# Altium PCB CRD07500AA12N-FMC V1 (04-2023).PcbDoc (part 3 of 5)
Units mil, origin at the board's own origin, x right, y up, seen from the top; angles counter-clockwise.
Board outline 8000 x 8000 mil, 4 copper layers (Top Layer, Layer 1, Layer 2, Bottom Layer), stack 107.988 mil thick; 393 components, 213 nets, 1142 pads, 380 vias.
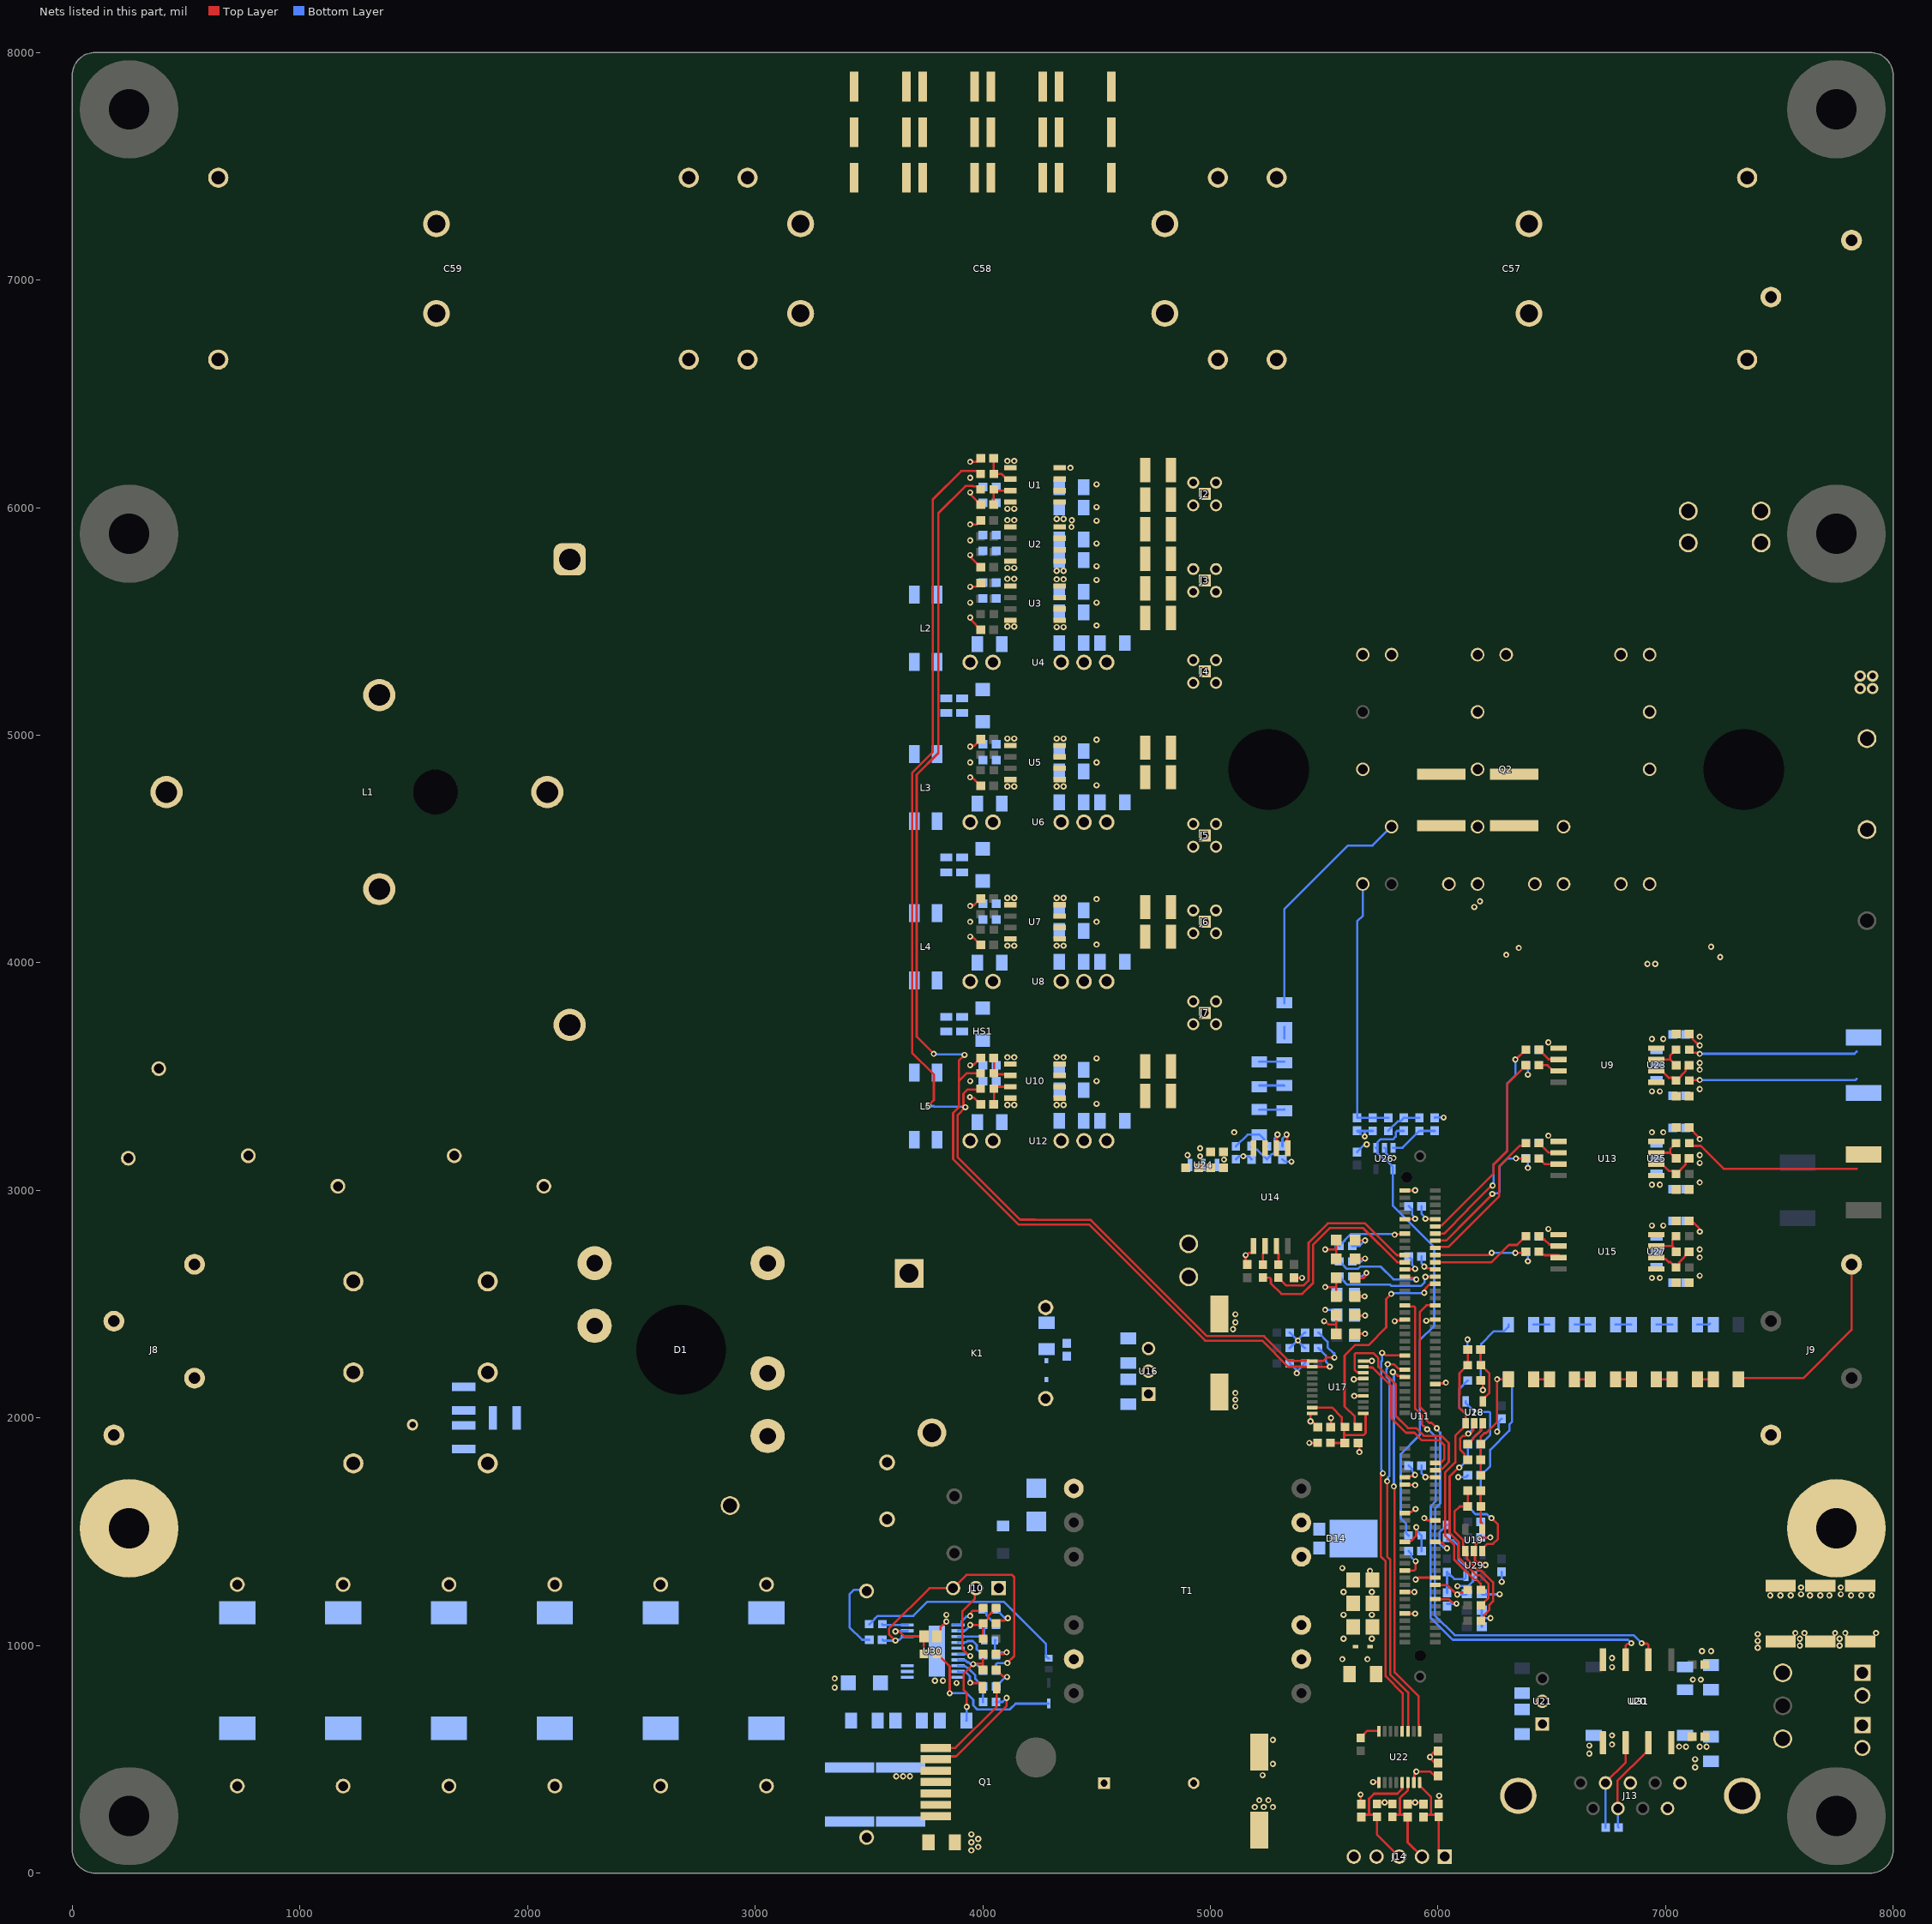
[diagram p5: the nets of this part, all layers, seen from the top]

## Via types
v1: diameter 27, hole 13, Top Layer to Bottom Layer, tented both sides, 367 vias
v2: diameter 50, hole 28, Top Layer to Bottom Layer, tented both sides, 13 vias

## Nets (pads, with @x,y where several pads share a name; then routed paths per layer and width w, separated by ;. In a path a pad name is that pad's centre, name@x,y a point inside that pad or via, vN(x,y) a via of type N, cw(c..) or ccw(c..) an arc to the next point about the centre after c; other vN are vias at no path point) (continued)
+5V: C32.1 C52.1 C65.1 C66.1 C68.1 C70.1 C72.1 C74.1 C79.1 C81.1 C86.1 C88.1 C96.1 C98.1 C114.1 C118.1 C120.1 C126.1 C146.1 J14.4 R78.2 R79.2 R80.2 R104.2 TP13.1 U1.1 U2.1 U3.1 U5.1 U7.1 U10.1 U11.48 U11.84 U11.98 U11.112 U11.120 U16.3 U17.20 U22.15 U31.2 | length 825.5
  Top Layer w10: U17.20@5447.8,2019.84 5442.87,2019.84 5440,2016.97 v1(5440,1985) 5443.25,1981.75 5450.15,1981.75 5471.9,1960 C32.1@5472.85,1960 ; R78.2@5732,303.62 5738.38,310 5793.62,310 R79.2@5800,303.62 ; v1(5810,2425) 5813.25,2428.25 5851.28,2428.25 U11.84@5855,2431.97 U11.84@5859.84,2436.81 ; U11.48@5855,1739.06 5859.84,1743.9 5889.02,1743.9 5894.74,1749.61 v1(5899.34,1749.61) ; U11.98@5855,2652.44 5856.28,2653.72 5898.72,2653.72 v1(5900,2655) ; U11.112@5855,2872.91 5856.04,2873.96 5898.96,2873.96 v1(5900,2875) ; U11.120@5855,2998.9 5855.55,2999.45 5899.45,2999.45 v1(5900,3000) ; U22.15@5896.18,397.8 5896.18,432.38 5905,441.2 v1(5905,445.8) 5965.62,445.8 5970.19,441.24 5971.14,441.24 5985,427.37 C52.1@5985,426.42 ; R80.2@6004,303.62 6005,304.62 v1(6005,340)
  Bottom Layer w10: v1(5505,2475) 5536.77,2475 5556.54,2455.23 R104.2@5556.54,2452 ; C126.1@5871.42,1790 5872.37,1790 5886.24,1776.14 5886.24,1767.31 5899.34,1754.21 v1(5899.34,1749.61) ; C118.1@5871.42,2710 5872.37,2710 5886.24,2696.14 5886.24,2673.36 5900,2659.6 v1(5900,2655) ; C114.1@5871.42,2930 5872.37,2930 5886.24,2916.14 5886.24,2893.36 5900,2879.6 v1(5900,2875)
  other v1: 5766,310 7120,850 7155,850 4108.46,3585 4138.46,3585 4108.46,4285 4138.46,4285 4108.46,4985 4138.46,4985 4108.46,5687.2 4138.46,5687.2 4108.46,5945 4138.46,5945 4108.46,6205 4138.46,6205
+5V_ISO: C49.1 C150.1 J13.9 U20.8 U31.5
  other v1: 7130,465 7130,500 6665,525 7090,555 7059.53,555.55 6665,560
+5V_LS: C19.1 C22.1 C109.1 U14.1 U24.1 | length 121.4
  Top Layer w10: v1(5335,3245) 5337.5,3242.5 5337.5,3187.07 U14.1@5340,3184.57
  Bottom Layer w10: C109.1@5317,3193.58 5317,3227 v1(5335,3245)
  other v1: 5060,3135
+5V_U_HS: C13.1 C16.1 C100.1 U9.1 U23.1 | length 70
  Top Layer w10: C13.1@7103.58,3686 7104.53,3686 7118.39,3672.14 7118.39,3666.61 7148,3637 v1(7150,3637)
  other v1: 6940,3435 6975,3435
+5V_V_HS: C18.1 C23.1 C113.1 U13.1 U25.1 | length 70.8
  Top Layer w10: C18.1@7103.58,3276 7104.53,3276 7146.75,3233.78 7146.75,3228.25 v1(7150,3225)
  other v1: 6940,3025 6975,3025
+5V_W_HS: C24.1 C28.1 C119.1 U15.1 U27.1 | length 77.5
  Top Layer w10: C24.1@7103.58,2876 7104.53,2876 7147.31,2833.21 7147.31,2821.75 v1(7150.57,2818.49)
  other v1: 6940,2615 6975,2615
+12V: C29.2 C43.1 C44.1 C45.1 C51.2 C121.1 C123.1 C149.1 D8.1 D12.2 D14.3 J11.1 J12.1 K1.3 L2.1 L3.1 L4.1 L5.1 R75.2 R82.2 R83.2 R84.2 R85.2 R87.2 R88.2 R103.2 TP8.1 U16.1 U21.1
  other v1: 5230,430 5275,480 5275,585 5580,940 5585,1030 5585,1135 5585,1235 5580,1340 5110,2050 5110,2080 5110,2110
+15V_LS: C21.1 C67.1 C71.1 C75.1 C76.1 U1.5 U2.5 U3.5 U4.7 U24.3
  other v1: 4900,3155 4325,5475 4355,5475 4325,5722 4355,5722 4325,5950.31 4355,5950.31
+15V_U_HS: C93.1 C99.1 C101.1 U10.5 U12.7 U23.3
  other v1: 4325,3375 4355,3375 6990,3665
+15V_V_HS: C89.1 C90.1 C107.1 U7.5 U8.7 U25.3
  other v1: 6990,3255 4325,4075 4355,4075
+15V_W_HS: C82.1 C83.1 C115.1 U5.5 U6.7 U27.3
  other v1: 6990,2845 4325,4775 4355,4775
-3V_LS: C64.2 C69.2 C73.2 C77.2 U1.8 U2.8 U3.8 U4.5
  other v1: 4325,5685 4355,5685 4390,5915 4391.58,5944.76 4385,6175
-3V_U_HS: C97.2 C102.2 U10.8 U12.5
  other v1: 4325,3585 4355,3585
-3V_V_HS: C87.2 C91.2 U7.8 U8.5
  other v1: 4325,4285 4355,4285
-3V_W_HS: C80.2 C84.2 U5.8 U6.5
  other v1: 4325,4985 4355,4985
A: F1.1 J8.1
A_FILT: C42.1 C134.1 D1.1 L1.4
A_FUSE: C39.1 C137.1 F1.2 L1.1 R128.2 RV1.2 RV3.2
AINN_U: C15.2 R34.2 U9.3 | length 151.5
  Top Layer w10: U9.3@6959.57,3575 7020.47,3575 ; C15.2@7046.42,3550 7045.47,3550 7020.47,3575 ; R34.2@7046.38,3618 7045.47,3618 7032.52,3605.04 7032.52,3604.14 7020.47,3592.09 7020.47,3575
AINN_V: C20.2 R42.2 U13.3 | length 149
  Top Layer w10: U13.3@6962.07,3165 7020.47,3165 ; C20.2@7046.42,3140 7045.47,3140 7020.47,3165 ; R42.2@7046.38,3208 7045.47,3208 7032.52,3195.04 7032.52,3194.14 7020.47,3182.09 7020.47,3165
AINN_W: C25.2 R47.2 U15.3 | length 145.7
  Top Layer w10: U15.3@6966.94,2755 7030.47,2755 ; C25.2@7046.42,2740 7045.47,2740 7030.47,2755 ; R47.2@7046.38,2808 7046.38,2798.91 7030,2782.53 7030,2755.47 7030.47,2755
AINP_U: C15.1 R38.2 U9.2 | length 183.3
  Top Layer w10: U9.2@6959.57,3525 6983.19,3525 7013.23,3494.96 7033.42,3494.96 R38.2@7046.38,3482 7047.28,3482 7069.76,3504.48 7069.76,3506.17 7088.76,3525.17 C15.1@7088.76,3536.14 ; C15.1@7103.58,3550 7105,3550 C15.1@7105,3545
AINP_V: C20.1 R45.2 U13.2 | length 194.9
  Top Layer w10: U13.2@6962.07,3115 6985.69,3115 7015.73,3084.96 7033.42,3084.96 R45.2@7046.38,3072 7047.28,3072 7069.76,3094.48 7069.76,3096.17 7088.76,3115.17 7088.76,3126.14 7102.63,3140 C20.1@7103.58,3140
AINP_W: C25.1 R51.2 U15.2 | length 189.1
  Top Layer w10: U15.2@6987.28,2710.91 6987.28,2700.91 6990,2698.19 7000,2698.19 7013.23,2684.96 7021.15,2684.96 7031.15,2674.96 7044.33,2674.96 R51.2@7047.28,2672 ; R51.2@7046.38,2662 7046.38,2670.25 7055.53,2670.25 7060.24,2674.96 7060.24,2684.11 7072.27,2696.14 7072.45,2696.14 7081.24,2704.92 7081.24,2706.8 7088.76,2714.33 7088.76,2725.19 C25.1@7103.58,2740
B: F2.1 J8.2
B_FILT: C41.1 C135.1 D1.2 L1.5
B_FUSE: C38.1 C138.1 F2.2 L1.2 R127.2 RV2.2 RV3.1
BLEED1: R3.2 R4.1 R7.2 R8.1 R11.2 R12.1
BLEED2: R1.2 R2.1 R5.2 R6.1 R9.2 R10.1
Bridge-: D1.5 K1.2 RV4.1 TP10.1
C: F3.1 J8.3
C_FILT: C40.1 C136.1 D1.3 L1.6
C_FUSE: C37.1 C139.1 F3.2 L1.3 R129.2 RV1.1 RV2.1
CAN_H: J13.7 R144.2 U20.7 | length 433.4
  Top Layer w10: J13.7@6788.54,284.09 6788.54,404.57 6911.69,527.72 6916.22,527.72 6925,536.5 U20.7@6925,572.91
  Bottom Layer w10: J13.7@6790.47,284.09 6790.47,203.15 R144.2@6793.62,200
CAN_L: J13.2 R144.1 U20.6 | length 410.8
  Top Layer w10: J13.2@6734.02,395.91 6825,486.89 U20.6@6825,572.91
  Bottom Layer w10: J13.2@6735.94,395.91 6735.94,200.43 R144.1@6736.38,200
CAN_RX: U11.87 U20.2 | length 2524.6
  Top Layer w10: U11.87@5988.86,2494.96 5949.96,2494.96 5920,2465 5920,2050 5950.24,2019.76 5950.24,1989.12 5960.86,1978.5 5971.5,1978.5 v1(5995,1955) ; v1(6895,1010) 6896.86,1008.14 6919.14,1008.14 6925,1002.28 U20.2@6925,937.09
  Bottom Layer w10: v1(5995,1955) 5995,1950.4 6010,1935.4 6010,1625 5988.5,1603.5 5988.5,1508.19 5987.04,1506.74 5987.04,1131.24 6073.28,1045 6860,1045 v1(6895,1010)
CAN_TX: U11.88 U20.3 | length 2483.2
  Top Layer w10: U11.88@5855,2494.96 5859.84,2490.12 5894.14,2490.12 5900,2484.26 5900,2040 5930.24,2009.76 5930.24,1970.54 5937.31,1963.47 5939.32,1963.47 v1(5952.79,1950) ; U20.3@6825,937.09 6825,1000 6831.75,1006.75 6846.75,1006.75 v1(6850,1010)
  Bottom Layer w10: v1(5952.79,1950) 5957.39,1950 5990,1917.39 5990,1633.28 5968.5,1611.78 5968.5,1516.48 5967.04,1515.02 5967.04,1122.96 6065,1025 6835,1025 v1(6850,1010)
CLK_I_U: R36.2 U11.109 | length 886.8
  Top Layer w10: U11.109@5988.86,2841.42 5993.7,2846.26 6016.88,2846.26 6245,3074.38 6245,3115 6305,3175 6305,3468.62 R36.2@6386.38,3550
CLK_I_V: R44.2 U11.105 | length 618.6
  Top Layer w10: U11.105@5988.86,2778.43 5989.65,2779.21 6036.21,2779.21 6140.48,2883.48 6238.85,2981.85 v1(6238.85,2984.15) ; v1(6343.11,3140) R44.2@6386.38,3140
  Bottom Layer w10: v1@6243.32,2984.15 v1(6238.85,2984.15) 6242.04,2987.35 6264.14,2987.35 6270,2993.21 6270,3105 6305,3140 v1(6343.11,3140)
CLK_I_W: R48.2 U11.101 | length 403.7
  Top Layer w10: U11.101@5988.86,2715.43 6221.73,2715.43 6231.52,2725.22 v1(6236.12,2725.22) ; v1(6340,2725) 6381.38,2725 R48.2@6386.38,2730
  Bottom Layer w10: v1(6236.12,2725.22) 6236.23,2725.11 6339.89,2725.11 v1(6340,2725)
CLK_V_DC: R50.2 U11.102 | length 839.9
  Top Layer w10: R50.2@5299,2616.38 5299,2615.47 5332.86,2581.61 5409.9,2581.61 5431.64,2603.35 5431.64,2769.93 5516.72,2855 5680,2855 5820,2715 5854.57,2715 U11.102@5855,2715.43
DAT_I_U: R33.2 U11.107 | length 999.3
  Top Layer w10: U11.107@5988.86,2809.92 6026.29,2809.92 6129.25,2912.88 6129.25,2914.86 6235.52,3021.13 v1(6240,3021.13) ; v1(6340,3575) 6342.47,3575 6385.47,3618 R33.2@6386.38,3618
  Bottom Layer w10: v1(6240,3021.13) 6243.25,3024.39 6243.25,3033.75 6245,3035.49 6245,3115 6305,3175 6305,3470 6340,3505 v1(6340,3575)
DAT_I_V: R41.2 U11.103 | length 665.9
  Top Layer w10: U11.103@5988.86,2746.93 5993.7,2751.77 6046.77,2751.77 6268.5,2973.5 6268.5,3105.7 6331.3,3168.5 6359.58,3196.77 6375.15,3196.77 R41.2@6386.38,3208
DAT_I_W: R46.2 U11.99 | length 444.8
  Top Layer w10: U11.99@5988.86,2683.94 6235.14,2683.94 6311.21,2760 6347.47,2760 6385.47,2798 R46.2@6386.38,2798
DAT_V_DC: R49.2 U11.100 | length 948.4
  Top Layer w10: R49.2@5231,2616.38 5260.19,2616.38 5266.04,2610.52 5266.04,2591.3 5312.35,2545 5403.28,2545 5451.64,2593.36 5451.64,2761.64 5525,2835 5670,2835 5821.06,2683.94 U11.100@5855,2683.94 U11.100@5853.35,2685.59
DC+: C8.1 C9.1 C36.1 C57.1 C58.1 C59.1 C61.1 C63.1 C151.1 C152.1 D1.4 D13.2 D16.1 J1.1 Q2.DC+_1 Q2.DC+_2 Q2.DC+_3 R4.2 R8.2 R12.2 R86.2 R143.2 T1.1 TP1.1 TP3.1 | length 1033.9
  Bottom Layer w10: R86.2@5325,3822.17 5325,4234.33 5605.67,4515 5713.03,4515 Q2.DC+_3@5796.06,4598.03
  other v1: 3350,815 3350,855
DC+0: R86.1 R90.2 | length 50.7
  Bottom Layer w10: R90.2@5325,3667.17 R86.1@5325,3717.83
DC+1: R90.1 R91.2 | length 110.3
  Bottom Layer w10: R91.2@5215,3565 5324.33,3565 R90.1@5325,3565.67
DC+2: R91.1 R92.2 | length 110.3
  Bottom Layer w10: R91.1@5215,3460.67 5324.33,3460.67 R92.2@5325,3460
DC+3: R92.1 R93.2 | length 110.3
  Bottom Layer w10: R93.2@5215,3355 5324.33,3355 R92.1@5325,3355.67
DC+4: R93.1 R97.2 R98.2 | length 189.9
  Bottom Layer w10: R98.2@5113,3193.62 5113,3194.53 5163.35,3244.88 R93.1@5215,3244.88 5216.44,3244.88 5236.04,3225.28 5236.04,3206.58 R97.2@5249,3193.62
DC+_D: D13.1 D15.1
DC-: C8.2 C9.2 C36.2 C46.2 C48.1 C53.1 C57.2 C58.2 C59.2 C60.2 C62.2 C141.2 C143.2 C144.2 C148.2 C151.2 C152.2 J1.2 J10.1 K1.1 Q2.DC-1 Q2.DC-2 Q2.DC-3 R1.1 R5.1 R9.1 R71.1 R74.1 R81.1 R138.2 RV5.2 T1.5 TP2.1 TP4.1 U30.15 U30.20 U30.EPAD | length 832.1
  Top Layer w10: C46.2@3798.57,1040 3814.33,1055.76 3814.33,1079.33 v1(3840,1105) ; C48.1@4058.58,894 C48.1@4058.58,894 4059.53,894 4088.53,865 4103.49,865 v1(4106.75,861.75) ; R74.1@4058.62,963 4093.4,963 4100.4,970 v1(4105,970) ; R71.1@4058.62,1097 4071.58,1109.96 4095.36,1109.96 4105.4,1120 v1(4110,1120)
  Bottom Layer w10: C36.2@3490,1239.34 3484.34,1245 3435,1245 3415,1225 3415,1080 3470,1025 C143.2@3501.42,1025 ; C144.2@4053.62,1023 C144.2@4053.62,1020 ; C144.2@4056.62,1023 C144.2@4053.62,1020 ; C148.2@4058.58,820 4059.53,820 4098.02,858.49 4103.49,858.49 v1(4106.75,861.75) ; C141.2@4058.58,1158 4059.53,1158 4094.27,1123.25 4106.75,1123.25 v1(4110,1120) ; v1(4105,970) 4058.62,970 4053.62,975 C144.2@4053.62,1020
  other v1: 3950,100 3980,115 3950,135 3980,150 3950,170 3620,425 3650,425 3680,425 3885,835 3790,845 3825,845 3944.99,990.95 3840,1135
EGND0: C134.2 C135.2 C136.2 C137.2 C138.2 C139.2 HS1.1 J8.4
EGND1: HS1.2 J9.1 R64.1 R65.1 R66.1
  other v1: 7460,1220 7505,1220 7550,1220 7635,1220 7680,1220 7720,1220 7815,1220 7860,1220 7905,1220 7595,1225 7770,1225 7595,1255 7770,1255
EQEP1A: C56.1 J14.1 R80.1 U22.16 | length 424.5
  Top Layer w10: U22.16@5921.77,397.8 5921.77,382.05 5969.98,333.84 5969.98,256.42 ; C56.1@5936,256.42 5969.98,256.42 ; J14.1@6030,72 6004,98 6004,256.38 6003.96,256.42 5969.98,256.42
EQEP1A_3V3: U11.68 U22.1 | length 1689.9
  Top Layer w10: v1(5801.77,2201.24) 5806.37,2201.24 5822.77,2184.84 5850.16,2184.84 U11.68@5855,2180 ; v1(5806.36,1699.27) 5809.62,1696.01 5809.62,1685.29 5810,1684.91 5810,881.57 5915,776.57 5915,652.74 5916.85,650.89 5916.85,624.92 U22.1@5919.57,622.2
  Bottom Layer w10: v1(5801.77,2201.24) 5805.02,2197.99 5805.02,2188.23 5806.36,2186.88 v1(5806.36,1699.27)
EQEP1B: C55.1 J14.2 R79.1 U22.14 | length 434.6
  Top Layer w10: R79.1@5800,256.38 5833.48,256.38 ; U22.14@5870.59,397.8 5867.87,395.08 5867.87,364.34 5833.14,329.6 5833.14,256.72 5833.48,256.38 ; J14.2@5930,72 5867,135 5867,256.42 5866.96,256.38 5833.48,256.38
EQEP1B_3V3: U11.70 U22.3 | length 1749.8
  Top Layer w10: v1(5777.02,1721.81) 5777.02,1391.26 5790,1378.28 5790,873.28 5869.32,793.96 5869.32,623.47 U22.3@5870.59,622.2 ; v1(5779.48,2235.79) 5779.92,2235.34 5807.98,2235.34 5826.98,2216.34 5850.16,2216.34 U11.70@5855,2211.5
  Bottom Layer w10: v1(5777.02,1721.81) 5780.28,1725.06 5780.28,1738.7 5786.36,1744.79 5786.36,2168.64 5773.27,2181.73 5773.27,2213.05 5776.22,2216 5776.22,2232.53 v1(5779.48,2235.79)
EQEP1I: C54.1 J14.3 R78.1 U22.13 | length 556.7
  Top Layer w10: C54.1@5663,256.42 5697.48,256.42 ; J14.3@5830,72 5732,170 5732,256.38 5731.96,256.42 5697.48,256.42 ; U22.13@5845,397.8 5842.28,395.08 5842.28,369.11 5822.07,348.9 5719.25,348.9 5697.48,327.13 5697.48,256.42
EQEP1I_3V3: U11.74 U22.4 | length 1817
  Top Layer w10: v1(5754.8,2285.96) 5759.4,2285.96 5770.88,2274.49 U11.74@5855,2274.49 ; v1(5757.86,1756.6) 5757.86,1751.99 5748.52,1742.66 5748.52,1391.48 5770,1370 5770,865 5845,790 U22.4@5845,622.2
  Bottom Layer w10: v1(5754.8,2285.96) 5754.8,2251.41 5750.98,2247.59 5750.98,1773.62 5754.61,1769.99 5754.61,1759.85 v1(5757.86,1756.6)
FLY+0: R142.2 R143.1
FLY+1: R141.2 R142.1
FLY_IN: D16.2 U30.1 U30.2 U30.3
FLY_S: Q1.3 Q1.4 Q1.5 Q1.6 Q1.7 R81.2
G1: J7.1 Q2.G1 R35.2 R40.2
G1H: R40.1 U10.6
G1L: R35.1 U10.7
G2: J2.1 Q2.G2 R13.2 R16.2
G2H: R16.1 U1.6
G2L: R13.1 U1.7
G3: J6.1 Q2.G3 R29.2 R32.2
G3H: R32.1 U7.6
G3L: R29.1 U7.7
G4: J3.1 Q2.G4 R17.2 R20.2
G4H: R20.1 U2.6
G4L: R17.1 U2.7
G5: J5.1 Q2.G5 R25.2 R28.2
G5H: R28.1 U5.6
G5L: R25.1 U5.7
G6: J4.1 Q2.G6 R21.2 R23.2
G6H: R23.1 U3.6
G6L: R21.1 U3.7
GD_DIS: R59.1 U11.93 | length 949.7
  Top Layer w10: R59.1@5648.62,1960 5647.72,1960 5634.76,1972.96 5634.76,2005.73 5590,2050.49 5590,2274.14 5635.86,2320 5695,2320 5772.5,2397.5 5772.5,2522.5 v1(5795,2545) ; v1(5940,2550) 5943.25,2553.25 5943.25,2567.03 5960.83,2584.61 5984.02,2584.61 U11.93@5988.86,2589.45
  Bottom Layer w10: v1(5795,2545) 5797.5,2547.5 5937.5,2547.5 v1(5940,2550)
GD_DIS_FILT: C33.1 R59.2 R60.2 U17.1 U17.19 | length 516.2
  Top Layer w10: U17.19@5447.8,2045.43 5534.9,2045.43 5577.52,2002.82 5577.52,1972.96 5590.47,1960 R59.2@5591.38,1960 5587.85,1956.47 5587.85,1925 ; R60.2@5530,1890 5587.85,1890 5587.85,1925 ; U17.1@5675,2020 5679.45,2020 5682.48,2016.97 5682.48,1933.34 5674.14,1925 5587.85,1925
GND: C1.2 C2.2 C3.2 C4.2 C5.2 C6.2 C7.2 C10.2 C11.2 C12.2 C14.2 C17.2 C26.2 C27.2 C29.1 C31.2 C32.2 C33.2 C34.2 C43.2 C44.2 C45.2 C47.2 C50.2 C51.1 C52.2 C53.2 C54.2 C55.2 C56.2 C65.2 C66.2 C68.2 C70.2 C72.2 C74.2 C79.2 C81.2 C86.2 C88.2 C94.2 C95.2 C96.2 C98.2 C103.2 C105.2 C108.2 C111.2 C112.2 C114.2 C116.2 C117.2 C118.2 C120.2 C121.2 C122.2 C123.2 C124.2 C126.2 C127.2 C128.2 C129.2 C130.2 C131.2 C132.2 C133.2 C140.2 C142.2 C146.2 C147.2 C149.2 D2.1 D3.1 D4.1 D5.1 D6.1 D7.1 D8.2 D9.1 D10.1 D11.1 J11.2 J12.2 J14.5 K1.4 L2.2 L3.2 L4.2 L5.2 R60.1 R64.2 R65.2 R66.2 R75.1 R96.1 R105.2 R113.1 R114.1 R115.1 R116.1 R117.1 R118.1 R133.1 T1.8 T1.9 TP9.1 TP11.1 U1.4 U2.4 U3.4 U5.4 U7.4 U9.5 U10.4 U11.10 U11.13 U11.16 U11.19 U11.22 U11.29 U11.35 U11.38 U11.46 U11.47 U11.65 U11.83 U11.97 U11.111 U13.5 U14.5 U15.5 U16.2 U17.4 U17.7 U17.10 U18.2 U19.2 U20.4 U21.2 U22.9 U26.2 U28.2 U29.2 U31.1 | length 4833.9
  Top Layer w10: v1(3943.5,3410) 3946.75,3406.75 3961.73,3406.75 3990.47,3378 C17.2@3991.42,3378 ; v1(3945,3550) 3948.25,3553.25 3961.73,3553.25 3990.47,3582 C14.2@3991.42,3582 ; v1(3945,4115) 3948.25,4111.75 3956.73,4111.75 3990.47,4078 C12.2@3991.42,4078 ; v1(3945,4250) 3948.25,4253.25 3961.73,4253.25 3990.47,4282 C11.2@3991.42,4282 ; v1(3945,4815) 3948.25,4811.75 3956.73,4811.75 3990.47,4778 C10.2@3991.42,4778 ; v1(3945,4950) 3948.25,4953.25 3961.73,4953.25 3990.47,4982 C7.2@3991.42,4982 ; v1(3945,5517.2) 3948.25,5513.95 3948.25,5506.22 3990.47,5464 C6.2@3991.42,5464 ; v1(3945,5652.2) 3970.75,5652.2 3972.68,5654.14 3977.56,5654.14 C5.2@3991.42,5668 ; v1(3945,5791.2) 3948.25,5787.95 3948.25,5780.22 3990.47,5738 C4.2@3991.42,5738 ; v1(3945,5926.2) 3973.68,5926.2 3990.47,5943 C3.2@3991.42,5943 ; v1(3945,6066.2) 3948.25,6062.95 3948.25,6055.22 3990.47,6013 C2.2@3991.42,6013 ; v1(3945,6201.2) 3970.75,6201.2 3972.68,6203.14 3977.56,6203.14 C1.2@3991.42,6217 ; C26.2@5163,2674.53 C26.2@5163,2673.58 5155,2681.58 v1(5155,2715) 5159.6,2715 5169.6,2725 5183.19,2725 5190,2731.81 U14.5@5190,2755.43 ; C27.2@5367,2616.42 5368.27,2615.15 v1(5403.14,2615.15) ; v1(5435,1890) R60.1@5471.38,1890 R60.1@5472.76,1890 ; v1(5500,2425) 5504.6,2425 5519.6,2410 5552.66,2410 5553.66,2411 ; v1(5505,2575) 5553.66,2575 ; v1(5505,2740) 5553.66,2740 ; C32.2@5530,1960 v1(5530,2000) ; D7.1@5553.66,2370 5553.66,2411 ; D6.1@5553.66,2452 5553.66,2411 ; D5.1@5553.66,2534 5553.66,2575 ; D4.1@5553.66,2616 5553.66,2575 ; D3.1@5553.66,2699 5553.66,2740 ; D2.1@5553.66,2781 5553.66,2740 ; v1(5630.14,2169.55) 5632.06,2171.47 5675.29,2171.47 U17.7@5676.32,2172.5 ; v1(5632.2,2096.61) U17.4@5672.2,2096.61 U17.4@5677.2,2096.61 ; C33.2@5645,1890 5655,1880 v1(5655,1850) ; v1(5660,345) 5660,306.58 C54.2@5663,303.58 ; U17.10@5672.2,2250.16 5672.41,2250.36 5709.29,2250.36 v1(5709.5,2250.57) ; v1(5715,400) 5738.23,400 U22.9@5740.43,397.8 ; U11.10@5855,1140.63 5855.31,1140.32 5899.69,1140.32 v1(5900,1140) ; U11.16@5855,1235.12 5855.06,1235.06 5896.44,1235.06 v1(5896.5,1235) ; U11.22@5855,1329.61 5855.2,1329.8 5896.26,1329.8 5902.12,1335.66 v1(5902.12,1370) ; U11.38@5855,1581.57 5859.84,1586.42 5883.96,1586.42 5897.26,1599.72 v1(5901.86,1599.72) ; U11.46@5855,1707.56 5856.28,1706.28 5898.72,1706.28 v1(5900,1705) ; C55.2@5867,303.58 5873.42,310 v1(5900,310) 5929.58,310 C56.2@5936,303.58 ; v1(5902.12,1290) 5906.72,1290 5914.83,1298.11 U11.19@5988.86,1298.11 ; v1(5940,1560) 5943.75,1560 5953.71,1550.04 5988.82,1550.04 U11.35@5988.86,1550.08 ; v1(5940,2665) 5944.6,2665 5952.32,2657.28 5984.02,2657.28 U11.97@5988.86,2652.44 ; v1(5945,1740) 5945.47,1739.53 5988.39,1739.53 U11.47@5988.86,1739.06 ; v1(5945,2875) 5946.04,2873.96 5987.81,2873.96 U11.111@5988.86,2872.91 ; v1(5948.5,2426.81) 5951.08,2429.39 5982.65,2429.39 5984.47,2427.58 U11.83@5988.86,2431.97 ; C52.2@5985,483.58 5985,484.53 5968.25,501.27 5968.25,506.75 v1(5965,510) 5968.25,513.25 5968.25,518.73 5985,535.47 C50.2@5985,536.42 ; U11.65@5988.11,2149.25 U11.65@5988.86,2148.5 5992.11,2151.75 6031.75,2151.75 v1(6035,2155) ; U11.13@5988.86,1203.62 6047.14,1203.62 6063.88,1186.89 6078.31,1186.89 v1(6081.56,1183.64) ; U11.29@5988.86,1455.59 5993.7,1450.75 6019.25,1450.75 6040,1430 v1(6040,1427) ; C34.2@6131.42,1816 6130.8,1816 6116.94,1829.86 6116.94,1841.41 6106.3,1852.04 6097.52,1860.83 6097.52,1909.17 6108.66,1920.31 6118.58,1920.31 6128.9,1930.63 v1@6134.09,1930.63 ; v1(6133.5,1930.63) 6136.75,1933.89 6144.65,1933.89 6155.76,1944.99 6155.76,1972.53 U18.2@6160,1976.77 ; U19.2@6157.4,1415 6166.02,1423.62 6166.02,1443.85 6195.99,1473.82 6228.82,1473.82 v1(6230,1475) ; U19.2@6162.32,1415 6162.32,1373.25 6168.18,1367.39 6190.15,1367.39 6203.97,1353.57 v1(6208.57,1353.57) ; C31.2@6188.58,2164 6197.55,2155.02 v1(6197.55,2122.54)
  Bottom Layer w10: R118.1@5348.62,2240 5349.53,2240 5376.75,2212.78 5376.75,2199.75 v1(5380,2196.5) ; R116.1@5348.62,2307 5349.53,2307 5382.53,2340 v1@5384.53,2340 ; R114.1@5348.62,2375 5349.53,2375 v1@5384.53,2340 ; v1@5380,2200 5380,2204.53 5415.47,2240 R117.1@5416.38,2240 ; R115.1@5416.38,2307 5415.47,2307 5385,2337.47 v1(5385,2340) ; R113.1@5416.38,2375 5415.47,2375 5385,2344.53 v1(5385,2340) ; C111.2@5645,3168.58 5645,3169.53 5673.97,3198.49 5683.49,3198.49 v1(5686.75,3201.75) ; C105.2@5658.58,3246.9 5658.58,3256.42 5650,3256.42 C105.2@5645,3261.42 5679.48,3261.42 ; v1@5675.12,3239.88 v1(5678.37,3236.63) 5678.37,3260.32 5679.48,3261.42 ; R96.1@5714,3261.38 R96.1@5714,3261.38 5679.48,3261.42 ; U26.2@5765,3187.24 5771.81,3180.43 5771.81,3163.16 5789.62,3145.34 5801.75,3145.34 v1(5805,3142.09) ; C130.2@5871.42,1415 5882.75,1403.67 5882.75,1389.37 v1(5902.12,1370) ; C126.2@5928.58,1790 5928.58,1756.42 v1(5945,1740) ; C118.2@5928.58,2710 5928.58,2678.71 5940,2667.29 v1(5940,2665) ; C114.2@5928.58,2930 5928.58,2896.02 5945,2879.6 v1(5945,2875) ; C103.2@5986,3318.58 5987.42,3320 v1(6025,3320) ; v1@6036.75,1423.25 6036.75,1425.65 6032.15,1430.25 6024.75,1430.25 6007.04,1447.96 6007.04,1498.45 6015.83,1507.24 6017.52,1507.24 6040,1529.72 R133.1@6040,1530.62 ; C133.2@6040,1183.42 6040.21,1183.64 v1(6081.56,1183.64) ; v1(6085.86,1261.04) 6086.74,1261.92 6134.44,1261.92 6153.19,1280.67 6153.19,1297.94 U29.2@6160,1304.76 ; v1(6089.02,1740) 6123.42,1740 C127.2@6131.42,1748 ; v1(6130,2345) 6130,2301.42 C122.2@6131.42,2300 ; v1@6136.71,1933.25 6151.38,1947.92 6151.38,1968.15 U28.2@6160,1976.77 ; C128.2@6189.53,1543 C128.2@6188.58,1543 C129.2@6188.58,1475 v1(6230,1475) ; C142.2@6192.55,1083 6192.55,1119 ; C140.2@6192.55,1155 6192.55,1119 ; C132.2@6192.55,1227 6194.55,1225 v1(6270.98,1225) ; v1(6230.98,1120) 6193.55,1120 6192.55,1119 ; v1(6260,1940) 6260,1944.6 6266.14,1950.74 6266.14,1982.56 C124.2@6280,1996.42 ; v1(6280,1280) C131.2@6280,1323.42 ; C117.2@6386.42,2730 6395,2721.42 v1(6395,2688.54) ; C112.2@6386.42,3140 6395,3131.42 v1(6395,3098.54) ; C95.2@6386.42,3550 6395,3541.42 v1(6395,3508.54) ; v1@5384.53,2340 v1(5385,2340)
  other v1: 5195,290 5235,290 5275,290 5215,320 5255,320 6765,905 5690,940 6765,945 7160,975 7200,975 7405,990 7590,1000 7765,1000 7405,1020 5709.5,1030 7590,1030 7765,1030 7405,1050 7570,1055 7610,1055 7745,1055 7790,1055 7925,1055 5709.5,1135 5709.5,1235 5701.17,1327.8 5100,2390 5110,2420 5110,2455 6485,2830 6485,3240 4108.46,3375 4138.46,3375 3945,3480 6485,3650 4108.46,4075 4138.46,4075 3945,4180 4108.46,4775 4138.46,4775 3945,4880 4108.46,5477.2 4138.46,5477.2 3945,5582.2 4108.46,5735 4138.46,5735 3945,5856.2 4108.46,5995 4138.46,5995 3945,6131.2
GND_ISO: C49.2 C150.2 J13.3 J13.5 J13.10 J13.11 U20.5 U31.4
  other v1: 7150,555 7180,555 6765,565 6765,605
LED_G: R100.2 U11.108 | length 314.8
  Top Layer w10: v1(5810,2805) 5812.46,2807.46 5852.54,2807.46 U11.108@5855,2809.92
  Bottom Layer w10: R100.2@5566.38,2756 5567.28,2756 5589.76,2778.48 5589.76,2780.17 5618.09,2808.5 5801.9,2808.5 5805.4,2805 v1(5810,2805)
LED_R: R102.2 U11.95 | length 469.1
  Top Layer w10: v1(5945,2620) 5945.47,2620.47 5988.39,2620.47 U11.95@5988.86,2620.94
  Bottom Layer w10: R102.2@5566.38,2621 5567.28,2621 5589.76,2598.52 5589.76,2596.83 5600.81,2585.78 5790.11,2585.78 5795.89,2580 5925,2580 5941.75,2596.75 5941.75,2616.75 v1(5945,2620)
LED_Y: R101.2 U11.96 | length 436.4
  Top Layer w10: U11.96@5855,2620.94 5859.84,2616.1 5892.8,2616.1 5900.4,2608.5 v1(5905,2608.5)
  Bottom Layer w10: R101.2@5566.38,2688 5567.28,2688 5589.76,2665.52 5589.76,2663.83 5598.55,2655.04 5648.7,2655.04 5659.15,2665.5 5747.19,2665.5 5804.19,2608.5 v1(5905,2608.5)
MID: C60.1 C61.2 C62.1 C63.2 R2.2 R3.1 R6.2 R7.1 R10.2 R11.1
N_X_I: C37.2 C38.2 C39.2 R127.1 R128.1 R129.1
  other v2: 1495,1970
N_X_O: C40.2 C41.2 C42.2
NetC30_1: C30.1 R52.2 U18.4 | length 254.9
  Top Layer w10: C30.1@6188.58,2300 R52.2@6188.62,2232 R52.2@6188.62,2232 6189.53,2232 6226.26,2195.26 6226.26,2110.95 6197.4,2082.09 U18.4@6197.4,2073.23
NetC30_2: C30.2 R52.1 R67.1 U18.1 | length 1192.2
  Top Layer w10: C30.2@6131.42,2300 C30.2@6131.42,2300 R52.1@6131.38,2232 6130.47,2232 6095,2196.53 6095,2103.26 6093.82,2102.08 6093.82,2044.38 6122.6,2015.6 U18.1@6122.6,1976.77 6122.6,1967.91 6076.61,1921.93 6076.61,1805.28 6031.5,1760.17 6031.5,1483.5 6071.22,1443.78 6071.22,1377.86 6159.83,1289.25 6170.75,1289.25 6187.9,1272.1 6187.9,1245.72 R67.1@6188.62,1245
NetC34_1: C34.1 R53.2 R61.1 R62.1 | length 505.9
  Top Layer w10: R62.1@6188.62,1748 C34.1@6188.58,1816 C34.1@6188.58,1816 R61.1@6188.62,1885 R61.1@6188.62,1885 6188.62,1917.96 6203.6,1932.94 6211.2,1932.94 6260,1981.74 v1(6260,2170) R53.2@6309.88,2170
NetC35_1: C35.1 R63.2 U19.4 | length 167.5
  Top Layer w10: C35.1@6188.58,1680 R63.2@6188.62,1611 R63.2@6188.62,1611 6188.62,1540.79 6202.32,1527.09 U19.4@6202.32,1518.23
NetC35_2: C35.2 R63.1 R70.1 U19.1 | length 716.4
  Top Layer w10: C35.2@6131.42,1680 R63.1@6131.38,1611 R63.1@6131.38,1611 6096,1611 6073.01,1588.01 6073.01,1500.82 6111.22,1462.61 6111.22,1423.78 6128.62,1406.38 6128.62,1378.67 6178.04,1329.25 6190.69,1329.25 6242.48,1277.45 6242.48,1193.92 6226,1177.43 6226,1156.35 6213.7,1144.04 6202.48,1132.83 6202.48,1121.96 6189.53,1109 R70.1@6188.62,1109
NetC46_1: C46.1 R73.2 U30.9 | length 252.9
  Top Layer w10: 3630.74,1064.91 3655.65,1040 C46.1@3741.43,1040 C46.1@3741.43,1040 R73.2@3741.38,963
  Bottom Layer w10: v1(3616.47,1061.66) 3617.47,1062.66 3667.94,1062.66 U30.9@3670.06,1064.78
NetC48_2: C48.2 R74.2 R139.2 R141.1 U30.17 | length 512.7
  Top Layer w10: v1(3930,730) 3930,791.45 3916.5,804.95 3916.5,876.5 v1(3958.27,918.27) 3960,920 4001.38,920 ; R74.2@4001.38,963 4001.38,920 ; C48.2@4005,890.42 C48.2@4001.42,894 C48.2@4001.42,894 4001.38,920
  Bottom Layer w10: U30.17@3891.22,936.61 3893.13,934.71 3924.38,934.71 3926.16,932.93 ; 3926.2,932.93 3931.79,927.34 3934.48,927.34 3936.37,925.45 3939.06,925.45 v1@3949.76,914.76 ; R141.1@3928.12,670 3930,671.88 v1(3930,730) ; v1(3958.27,918.27) 3961.52,915.01 3974.46,915.01 4000.47,889 R139.2@4001.38,889
NetC78_1: C78.1 L2.4 U4.1
NetC78_2: C78.2 L2.3 U4.2
NetC85_1: C85.1 L3.4 U6.1
NetC85_2: C85.2 L3.3 U6.2
NetC92_1: C92.1 L4.4 U8.1
NetC92_2: C92.2 L4.3 U8.2
NetC103_1: C103.1 R94.2 U26.3 | length 214.9
  Bottom Layer w10: U26.3@5802.4,3187.24 5844.77,3187.24 5918,3260.47 R94.2@5918,3261.38 C103.1@5986,3261.42 C103.1@5986,3261.42
NetC104_1: C104.1 R134.1 U26.1 U26.4 | length 2064.7
  Bottom Layer w10: C104.1@5850,3261.42 5820.81,3261.42 5814.96,3255.57 5814.96,3236.3 5802.55,3223.9 5746.98,3223.9 5734.41,3211.33 5734.41,3194.06 U26.1@5727.6,3187.24 5734.41,3180.43 5734.41,3163.16 5761.28,3136.28 5768.72,3136.28 5802.4,3102.6 U26.4@5802.4,3092.76 5802.4,2932.29 5983.39,2751.3 5983.39,2404.6 5920,2341.21 5920,2146.86 5920.49,2146.37 5920.49,1925.49 5836.61,1841.61 5836.61,1558.39 5860,1535 5860,1494.38 R134.1@5871.38,1483
NetC104_2: C104.2 R94.1 R95.2 | length 160.8
  Bottom Layer w10: R95.2@5782,3261.38 5782,3262.28 5804.48,3284.76 5806.17,3284.76 5825.17,3303.76 5836.14,3303.76 5850,3317.63 C104.2@5850,3318.58 R94.1@5918,3318.62 R94.1@5918,3318.62
NetC106_1: C106.1 L5.4 U12.1
NetC106_2: C106.2 L5.3 U12.2
NetC110_1: C110.1 R97.1 U14.2 | length 285.6
  Top Layer w10: U14.2@5290,3184.57 5292.47,3187.04 5292.47,3242.58 v1(5294.94,3245.05)
  Bottom Layer w10: C110.1@5181,3193.58 5181,3192.63 5194.86,3178.76 5205.83,3178.76 5224.83,3159.76 5226.52,3159.76 R97.1@5248.96,3137.33 ; R97.1@5248,3136.38 R97.1@5248.96,3137.33 ; R97.1@5249,3136.38 5249,3137.28 R97.1@5248.96,3137.33 ; v1(5294.94,3245.05) 5294.94,3240.45 5282.86,3228.37 5282.86,3167.55 5274.08,3158.76 5270.39,3158.76 R97.1@5248.96,3137.33
NetC122_1: C122.1 R111.2 R119.1 R126.1 | length 322.5
  Bottom Layer w10: R126.1@6188.62,2164 R119.1@6188.62,2232 C122.1@6188.58,2300 C122.1@6188.58,2300 6190,2301.42 6190,2325 6245.55,2380.55 6290.28,2380.55 6309.88,2400.16 R111.2@6309.88,2410
NetC125_1: C125.1 R130.2 U28.4 | length 357
  Bottom Layer w10: U28.4@6122.6,2073.23 6122.6,2064.37 6160,2026.97 6224.14,2026.97 6230,2021.11 6230,1926.42 6203.39,1899.81 6203.39,1898.86 6189.53,1885 C125.1@6188.58,1885 R130.2@6188.62,1816 R130.2@6188.62,1816
NetC125_2: C125.2 R68.1 R130.1 U28.1 | length 958.4
  Top Layer w10: v1(6093.63,1782) 6090.71,1782 6051.5,1742.79 6051.5,1493.5 6091.22,1453.78 6091.22,1386.15 6168.12,1309.25 6182.4,1309.25 6222.48,1269.17 6222.48,1209.96 6189.53,1177 R68.1@6188.62,1177
  Bottom Layer w10: v1(6093.63,1782) 6096.47,1782 6130.47,1816 R130.1@6131.38,1816 R130.1@6131.38,1816 C125.2@6131.42,1885 6132.37,1885 6153.76,1906.39 6153.76,1910.08 6188.78,1945.09 6188.78,1968.15 U28.1@6197.4,1976.77
NetC127_1: C127.1 R125.2 R131.1 R132.1 | length 622.3
  Bottom Layer w10: R132.1@6188.62,1611 R131.1@6188.62,1680 C127.1@6188.58,1748 C127.1@6188.58,1748 6189.53,1748 6230,1788.47 6230,1860 6313.86,1943.86 6313.86,1971.36 6325,1982.5 6325,2154.88 R125.2@6309.88,2170
NetC133_1: C133.1 R133.2 R135.1 U29.3 | length 404.9
  Bottom Layer w10: C133.1@6040,1230.58 R135.1@6040,1322.47 ; R135.1@6040,1323.38 R135.1@6040,1322.47 ; R133.2@6040,1463.38 6040.48,1462.9 6067.1,1462.9 6090,1440 6090,1377.16 6122.6,1344.57 U29.3@6122.6,1304.76 6122.6,1299.01 6115.79,1292.2 6071.61,1292.2 6054.3,1309.52 6052.96,1309.52 R135.1@6040,1322.47
NetC141_1: C141.1 R137.1 | length 92.8
  Bottom Layer w10: C141.1@4001.42,1158 4002.37,1158 4016.24,1144.14 4016.24,1133.17 4035.24,1114.17 4035.24,1112.48 4057.72,1090 R137.1@4058.62,1090
NetC143_1: C143.1 J10.3 R139.1 U30.8 | length 1305.5
  Top Layer w10: v1(3616.61,1021.5) 3616.32,1021.5 3587.97,1049.85 3587.97,1073.46 3766.51,1252 J10.3@3870,1252 3928,1310 4129.14,1310 4138.5,1300.64 4138.5,953.5 v1(4108.04,923.04)
  Bottom Layer w10: C143.1@3560,1025 3563.5,1021.5 v1(3616.61,1021.5) ; v1@3616.63,1021.63 3619.88,1024.88 3634.32,1024.88 3648.42,1038.98 U30.8@3670.28,1038.98 ; R139.1@4058.62,889 4058.62,917.19 4064.48,923.04 v1(4108.04,923.04)
NetC144_1: C144.1 R137.2 U30.13 | length 164.7
  Bottom Layer w10: U30.13@3891.22,1038.98 3891.7,1039.45 4000.83,1039.45 4006.38,1045 4006.38,1085 R137.2@4001.38,1090
NetC145_2: C145.2 R136.2 | length 965.3
  Bottom Layer w10: R136.2@3501.38,1093 3502.28,1093 3524.76,1115.48 3524.76,1117.17 3537.59,1130 3695,1130 3756.96,1191.96 4093.04,1191.96 4277.28,1007.72 4277.28,953.39 4287.05,943.62 C145.2@4290,943.62
NetC148_1: C148.1 R140.1 U30.18 | length 225.2
  Bottom Layer w10: U30.18@3891.22,911.02 3893.13,909.12 3921.72,909.12 3923.5,907.34 3926.2,907.34 3931.79,901.75 3934.48,901.75 3967.52,868.71 3967.52,853.91 3973.5,847.92 3973.5,846.97 4000.47,820 C148.1@4001.42,820 C148.1@4001.42,820 R140.1@4001.38,752
NetD2_2: D2.2 R100.1 | length 110.4
  Top Layer w10: D2.2@5636.34,2781 5637.34,2780 v1(5680,2780)
  Bottom Layer w10: R100.1@5623.62,2756 5656,2756 v1(5680,2780)
NetD3_2: D3.2 R101.1 | length 105.4
  Top Layer w10: D3.2@5636.34,2699 5637.34,2700 v1(5680,2700)
  Bottom Layer w10: R101.1@5623.62,2688 5663.4,2688 5675.4,2700 v1(5680,2700)
NetD4_2: D4.2 R102.1 | length 134.1
  Top Layer w10: D4.2@5636.34,2616 5637.34,2615 5674.14,2615 5682.73,2623.59 5682.73,2633.75 v1(5685.98,2637)
  Bottom Layer w10: R102.1@5623.62,2621 5665.38,2621 5681.38,2637 v1(5685.98,2637)
NetD5_2: D5.2 R103.1 | length 86.2
  Top Layer w10: D5.2@5636.34,2534 v1(5678,2534)
  Bottom Layer w10: R103.1@5633.46,2534 v1(5678,2534)
NetD6_2: D6.2 R104.1 | length 91.9
  Top Layer w10: D6.2@5636.34,2452 5638.34,2450 v1(5680,2450)
  Bottom Layer w10: R104.1@5633.46,2452 5635.46,2450 v1(5680,2450)
NetD7_2: D7.2 R112.1 | length 90.2
  Top Layer w10: D7.2@5636.34,2370 v1(5680,2370)
  Bottom Layer w10: R112.1@5633.46,2370 v1(5680,2370)
NetD9_2: D9.2 R82.1 R83.1
NetD10_2: D10.2 R84.1 R85.1
NetD11_2: D11.2 R87.1 R88.1
NetD12_1: D12.1 R105.1
NetD14_1,2: D14.1 D14.2 T1.10 T1.11
NetD17_1: D17.1 R73.1 | length 687.8
  Top Layer w10: R73.1@3798.62,963 3799.53,963 3852.53,910 3855,910 v1(3855,790)
  Bottom Layer w10: v1(3855,790) 3930,790 3958.5,761.5 3958.5,736.85 3976.3,719.04 4118.87,719.04 4144.55,744.72 D17.1@4290,744.72
NetJ10_2: J10.2 U30.16 | length 397.4
  Top Layer w10: v1(3945.44,953.95) 3941.69,953.95 3910,985.64 3910,1150 3965.5,1205.5 3965.5,1247.5 J10.2@3970,1252
  Bottom Layer w10: U30.16@3891.22,962.2 3932.59,962.2 3940.84,953.95 v1(3945.44,953.95)
NetQ1_1: Q1.1 R76.2 | length 463.4
  Top Layer w10: Q1.1@3762.01,562.72 3774.72,550 3795,550 3880,550 4061.5,731.5 R76.2@4061.5,815
NetQ1_2: Q1.2 R140.2 | length 496.2
  Top Layer w10: Q1.2@3795,500 3807.72,512.72 3882.72,512.72 4105,735 v1(4105,770)
  Bottom Layer w10: R140.2@4058.62,752 4087,752 v1(4105,770)
NetR33_1: R33.1 U9.6 | length 105.2
  Top Layer w10: R33.1@6443.62,3618 6444.53,3618 6457.48,3605.04 6457.48,3604.14 6485.86,3575.76 6529.67,3575.76 U9.6@6530.43,3575
NetR36_1: R36.1 U9.7 | length 97.2
  Top Layer w10: R36.1@6443.62,3550 6481.81,3550 6506.81,3525 U9.7@6530.43,3525
NetR41_1: R41.1 U13.6 | length 105.2
  Top Layer w10: R41.1@6443.62,3208 6444.53,3208 6457.48,3195.04 6457.48,3194.14 6485.86,3165.76 6529.67,3165.76 U13.6@6530.43,3165
NetR44_1: R44.1 U13.7 | length 97.2
  Top Layer w10: R44.1@6443.62,3140 6444.53,3140 6469.53,3115 U13.7@6530.43,3115
NetR46_1: R46.1 U15.6 | length 116.8
  Top Layer w10: R46.1@6443.62,2798.91 6457.48,2785.04 6466.58,2785.04 6489.81,2761.81 6528.34,2761.81 U15.6@6540.15,2750
NetR48_1: R48.1 U15.7 | length 102.5
  Top Layer w10: R48.1@6443.62,2740 6443.62,2730.91 6457.48,2717.04 6466.58,2717.04 6468.62,2715 U15.7@6530.43,2715
NetR49_1: R49.1 U14.6 | length 85.5
  Top Layer w10: R49.1@5231,2673.62 5231,2722.81 5240,2731.81 U14.6@5240,2755.43
NetR50_1: R50.1 U14.7 | length 86.4
  Top Layer w10: U14.7@5290,2755.43 5290,2731.81 5300,2721.81 5300,2680 5299,2679 R50.1@5299,2673.62
NetR61_2: R61.2 U18.3 | length 119.6
  Top Layer w10: R61.2@6131.38,1885 6132.28,1885 6154.76,1907.48 6154.76,1911.59 6168.62,1925.45 6168.62,1926.24 6188.78,1946.4 6188.78,1968.15 U18.3@6197.4,1976.77
NetR69_1: R69.1 U30.11 | length 179.6
  Top Layer w10: v1(3945,1130) 3948.25,1133.25 3948.25,1145.32 3954.98,1152.04 3988.42,1152.04 R69.1@4001.38,1165
  Bottom Layer w10: U30.11@3868.95,1092.06 3870.86,1090.16 3905.36,1090.16 3907.27,1092.06 3907.27,1106.21 3927.88,1126.82 3941.82,1126.82 v1(3945,1130)
NetR69_2: R69.2 R71.2 R72.1 U30.12 | length 283.3
  Top Layer w10: v1(3945,1090) 3995.28,1090 R71.2@4001.38,1096.09 ; R72.1@4001.38,1030 R71.2@4001.38,1096.09 ; R69.2@4057.72,1165 4035.24,1142.52 4035.24,1140.83 4024.76,1130.35 4024.76,1119.48 R71.2@4001.38,1096.09
  Bottom Layer w10: U30.12@3891.22,1064.57 3893.13,1066.47 3924.42,1066.47 3945,1087.05 v1(3945,1090)
NetR76_1: R76.1 U30.19 | length 157.4
  Top Layer w10: v1(3945,836.12) 3946.51,834.61 3987.76,834.61 3998.5,823.86 R76.1@3998.5,815
  Bottom Layer w10: U30.19@3891.22,885.43 3893.13,883.53 3921.72,883.53 3923.5,881.75 3926.2,881.75 3943.33,864.62 3943.33,837.79 v1(3945,836.12)
NetR77_1: R77.1 U22.8 | length 95.1
  Top Layer w10: R77.1@5660,593.62 5660,594.53 5690.47,625 5737.64,625 U22.8@5740.43,622.2
NetR126_2: R126.2 U28.3 | length 216.3
  Bottom Layer w10: U28.3@6122.6,1976.77 6122.6,2017.4 6104.41,2035.59 6102.61,2035.59 6093.82,2044.38 6093.82,2127.35 6130.47,2164 R126.2@6131.38,2164
NetR132_2: R132.2 U19.3 | length 325.3
  Top Layer w10: U19.3@6194.8,1415 6194.8,1423.86 6217.44,1446.5 6241.81,1446.5 6263.5,1468.2 6263.5,1531.5 v1(6235,1560)
  Bottom Layer w10: R132.2@6131.38,1611 6132.28,1611 6154.76,1588.52 6154.76,1586.83 6164.73,1576.86 6214.6,1576.86 6231.47,1560 v1(6235,1560)
NetR136_1: R136.1 U30.10 | length 112.8
  Bottom Layer w10: R136.1@3558.62,1093 3561.46,1090.16 U30.10@3670.28,1090.16
NetR138_1: R138.1 U30.14 | length 150.5
  Bottom Layer w10: U30.14@3891.22,1013.39 3893.13,1015.29 3929.03,1015.29 3933.19,1019.45 3956.8,1019.45 3973.49,1002.76 3973.49,982.98 4000.47,956 R138.1@4001.38,956
NTC: C105.1 Q2.NTC2 R95.1 R96.2 | length 1174.9
  Bottom Layer w10: Q2.NTC2@5670.08,4346.06 5670.08,4207.58 5645,4182.5 C105.1@5645,3318.58 R96.2@5714,3318.62 R96.2@5714,3318.62 R95.1@5782,3318.62
NTC_MEAS: C130.1 R134.2 U11.30 | length 213.1
  Top Layer w10: U11.30@5855,1455.59 5859.84,1460.43 5883.02,1460.43 5904.64,1482.05 v1(5904.64,1519.52)
  Bottom Layer w10: v1(5904.64,1519.52) 5907.89,1516.27 5907.89,1502.82 5927.72,1483 R134.2@5928.62,1483 R134.2@5928.62,1483 C130.1@5928.58,1415
S1: C13.2 C16.2 C93.2 C97.1 C99.2 C100.2 C101.2 C102.1 J7.2 J7.3 J7.4 J7.5 Q2.S1 U9.4 U12.6 U23.2
  other v1: 4500,3380 7150,3445 4500,3480 7150,3530 7150,3560 4500,3580 6940,3665 7150.15,3675.15
S3: C18.2 C23.2 C87.1 C89.2 C90.2 C91.1 C107.2 C113.2 J6.2 J6.3 J6.4 J6.5 Q2.S3 U8.6 U13.4 U25.2
  other v1: 7150,3035 7150,3120 7150,3155 6940,3255 6920,3995 6955,3995 6300,4035 6355,4065 4500,4080 4500,4180 4500,4280
S5: C24.2 C28.2 C80.1 C82.2 C83.2 C84.1 C115.2 C119.2 J5.2 J5.3 J5.4 J5.5 Q2.S5 U6.6 U15.4 U27.2
  other v1: 7150,2625 7150,2705 7150,2740 6940,2845 7240,4025 7200,4070 6160,4245 6185,4270 4500,4780 4500,4880 4500,4980
SL: C19.2 C21.2 C22.2 C64.1 C67.2 C69.1 C71.2 C73.1 C75.2 C76.2 C77.1 C109.2 C110.2 J2.2 J2.3 J2.4 J2.5 J3.2 J3.3 J3.4 J3.5 J4.2 J4.3 J4.4 J4.5 Q2.S2 Q2.S4 Q2.S6 R98.1 U4.6 U14.3 U14.4 U24.2 | length 123.3
  Bottom Layer w10: R98.1@5113,3136.38 5113,3137.04 5125.96,3150 v1(5145,3150) 5167.42,3150 C110.2@5181,3136.42 ; C109.2@5317,3136.42 5327.38,3126.04 v1(5356.34,3126.04)
  other v1: 4955,3150 4955,3185 5105,3255 4500,5482.2 4500,5582.2 4500,5682.2 4500,5742.2 4500,5842.2 4500,5942.2 4500,6002.2 4500,6102.2
U: Q2.U R34.1 R89.1 TP5.1 | length 747.8
  Top Layer w10: R34.1@7103.62,3618 7116.58,3605.04 7140.36,3605.04 7145.4,3600 v1(7150,3600)
  Bottom Layer w10: v1(7150,3600) 7830.35,3600 7840,3609.65
  other v2: 7855,5205 7910,5205 7855,5260 7910,5260
U0: R57.1 R58.2 | length 69.8
  Top Layer w10: R57.1@7140.12,2170 R58.2@7209.88,2170
U1: R56.1 R57.2 | length 69.8
  Top Layer w10: R56.1@6960.12,2170 R57.2@7029.88,2170
U2: R55.1 R56.2 | length 69.8
  Top Layer w10: R55.1@6780.12,2170 R56.2@6849.88,2170
U3: R54.1 R55.2 | length 69.8
  Top Layer w10: R54.1@6600.12,2170 R55.2@6669.88,2170
U4: R53.1 R54.2 | length 69.8
  Top Layer w10: R53.1@6420.12,2170 R54.2@6489.88,2170
U_HS: R15.1 R37.1 R115.2 U17.12 | length 5550.4
  Top Layer w10: v1(3785,3600) 3710,3675 3710,4826.72 3805,4921.72 3805,5975 3924.7,6094.7 3956.81,6094.7 3957.55,6093.96 3978.42,6093.96 R15.1@3991.38,6081 ; v1(3920,3595) 3895,3570 3895,3480 ; R37.1@3991.38,3514 3929,3514 3895,3480 ; v1(5525,2225) 5524.78,2224.78 5448.01,2224.78 U17.12@5447.8,2224.57 5447.36,2225 5341.72,2225 5227.42,2339.29 4977.42,2339.29 4466.72,2850 4156.72,2850 3870,3136.72 3870,3339.78 3895,3364.78 3895,3480
  Bottom Layer w10: v1(3785,3600) 3787.5,3597.5 3917.5,3597.5 v1(3920,3595) ; R115.2@5473.62,2307 5474.53,2307 5507.48,2274.04 5507.48,2247.12 5525,2229.6 v1(5525,2225)
U_HS+_FILT: C14.1 R37.2 U10.2 | length 136.1
  Top Layer w10: R37.2@4048.62,3514 4050,3515.38 4050,3580.58 C14.1@4048.58,3582 ; R37.2@4058.58,3514.04 4062.62,3510 4116.73,3510 U10.2@4121.73,3505
U_HS-_FILT: C2.1 R15.2 U1.3 | length 143.6
  Top Layer w10: C2.1@4048.58,6013 R15.2@4048.62,6081 R15.2@4048.62,6081 4054.62,6075 U1.3@4121.73,6075
U_HS_PWM: U11.49 U17.8 | length 952.3
  Top Layer w10: U17.8@5672.2,2198.98 5669.49,2201.69 5643.52,2201.69 5633.58,2211.63 5633.58,2279.14 5639.44,2285 5715.46,2285 5738,2262.46 5738,2224.7 5815,2147.7 5815,2007.84 5867.84,1955 5904.69,1955 5938.19,1921.5 6015.22,1921.5 6026.83,1909.88 6026.98,1909.88 6047.48,1889.38 6047.48,1806.07 6032.18,1790.77 6032.18,1790.69 6016.88,1775.39 5993.7,1775.39 U11.49@5988.86,1770.55
U_LS: R14.1 R39.1 R113.2 U17.11 | length 5746.4
  Top Layer w10: v1(3761.5,3370.61) 3761.5,3372.71 3785,3396.21 3785,3509.8 3690,3604.8 3690,4835 3780,4925 3780,6035 3905.86,6160.86 3978.52,6160.86 R14.1@3991.38,6148 ; R39.1@3991.38,3446 3988.88,3443.5 3933.19,3443.5 3915,3425.31 3915,3365 v1(3923.5,3365) 3890,3331.5 3890,3145 4164,2871 4229,2871 4230,2870 4475,2870 4985.71,2359.29 5235.71,2359.29 5345,2250 5447.64,2250 U17.11@5447.8,2250.16 5495.99,2250.16 5510.83,2265 v1(5545,2265)
  Bottom Layer w10: v1(3761.5,3370.61) 3784.39,3370.61 3787.5,3367.5 3921,3367.5 v1(3923.5,3365) ; R113.2@5473.62,2375 5474.53,2375 5515,2334.53 5515,2310 5540.24,2284.76 5545,2284.76 v1(5545,2265)
U_LS+_FILT: C1.1 R14.2 U1.2 | length 151.7
  Top Layer w10: C1.1@4048.58,6217 C1.1@4048.58,6217 R14.2@4048.62,6148 4082.98,6148 4105.98,6125 U1.2@4121.73,6125
U_LS-_FILT: C17.1 R39.2 U10.3 | length 136.1
  Top Layer w10: C17.1@4048.58,3378 4050,3379.42 4050,3444.62 R39.2@4048.62,3446 ; R39.2@4058.58,3445.96 4058.62,3446 4067.62,3455 U10.3@4121.73,3455
U_LS_PWM: U11.51 U17.9 | length 675.5
  Top Layer w10: U17.9@5685,2225 5688.15,2221.85 5702.54,2221.85 5703.04,2221.35 5713.07,2221.35 5795,2139.42 5795,1999.56 5859.56,1935 5896.29,1935 5929.79,1901.5 6006.93,1901.5 6018.55,1889.88 6018.69,1889.88 6027.48,1881.1 6027.48,1817.49 6016.88,1806.89 5993.7,1806.89 U11.51@5988.86,1802.05
U_MEAS: C132.1 R67.2 U11.17 | length 212.1
  Top Layer w10: U11.17@5988.86,1266.61 5989.67,1265.81 6040.79,1265.81 6082.54,1224.05 v1(6084.98,1224.05) ; v1@6085,1225 6089.6,1225 6096.64,1232.04 6118.42,1232.04 R67.2@6131.38,1245
  Bottom Layer w10: v1(6084.98,1224.05) 6124.5,1224.05 C132.1@6127.45,1227
U_OUT: J9.4 R38.1 R58.1 R89.2 | length 1614.7
  Top Layer w10: R38.1@7103.62,3482 7106.62,3485 v1(7150,3485) ; R58.1@7320.12,2170 7325.12,2175 7605,2175 7817.17,2387.17 J9.4@7817.17,2675
  Bottom Layer w10: v1(7150,3485) 7834.65,3485 7840,3490.35
V: Q2.V R42.1 R43.1 TP6.1 | length 783.3
  Top Layer w10: R42.1@7103.62,3208 7116.58,3195.04 7154.96,3195.04 7255.35,3094.65 7840,3094.65
V0: R106.2 R107.1 | length 57.6
  Bottom Layer w10: R107.1@7140,2410 7190.51,2410 R106.2@7195.51,2415
V1: R107.2 R108.1 | length 69.8
  Bottom Layer w10: R108.1@6960,2410 R107.2@7029.76,2410
V2: R108.2 R109.1 | length 69.6
  Bottom Layer w10: R109.1@6780.12,2410 R108.2@6849.76,2410
V3: R109.2 R110.1 | length 69.8
  Bottom Layer w10: R110.1@6600.12,2410 R109.2@6669.88,2410
V4: R110.2 R111.1 | length 69.8
  Bottom Layer w10: R111.1@6420.12,2410 R110.2@6489.88,2410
